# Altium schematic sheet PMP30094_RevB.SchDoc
size 431 x 279 mm; Date: Not shown in title block; ApprovedBy: Not shown in title block; CheckedBy: Not shown in title block; Author: Not shown in title block; CompanyName: Not shown in title block; Engineer: Not shown in title block; Organization: Not shown in title block; Address1: Not shown in title block; Address2: Not shown in title block; Address3: Not shown in title block; Address4: Not shown in title block; DocumentNumber: 1; Revision: Use project parameter SCH_Rev; SheetNumber: 2; SheetTotal: 3; PageSetup: Record=PageOptions¦CenterHorizontal=True¦CenterVertical=True¦PrintScale=0.64¦XCorrection=1.00¦YCorrection=1.00¦PrintKind=0¦BorderSize=5000000¦LeftOffset=0¦BottomOffset=0¦Orientation=2¦PaperLength=1000¦PaperWidth=1000¦Scale=100¦PaperSource=15¦PrintQuality=600¦MediaType=1¦DitherType=10¦PrintScaleMode=1¦PaperKind=Letter
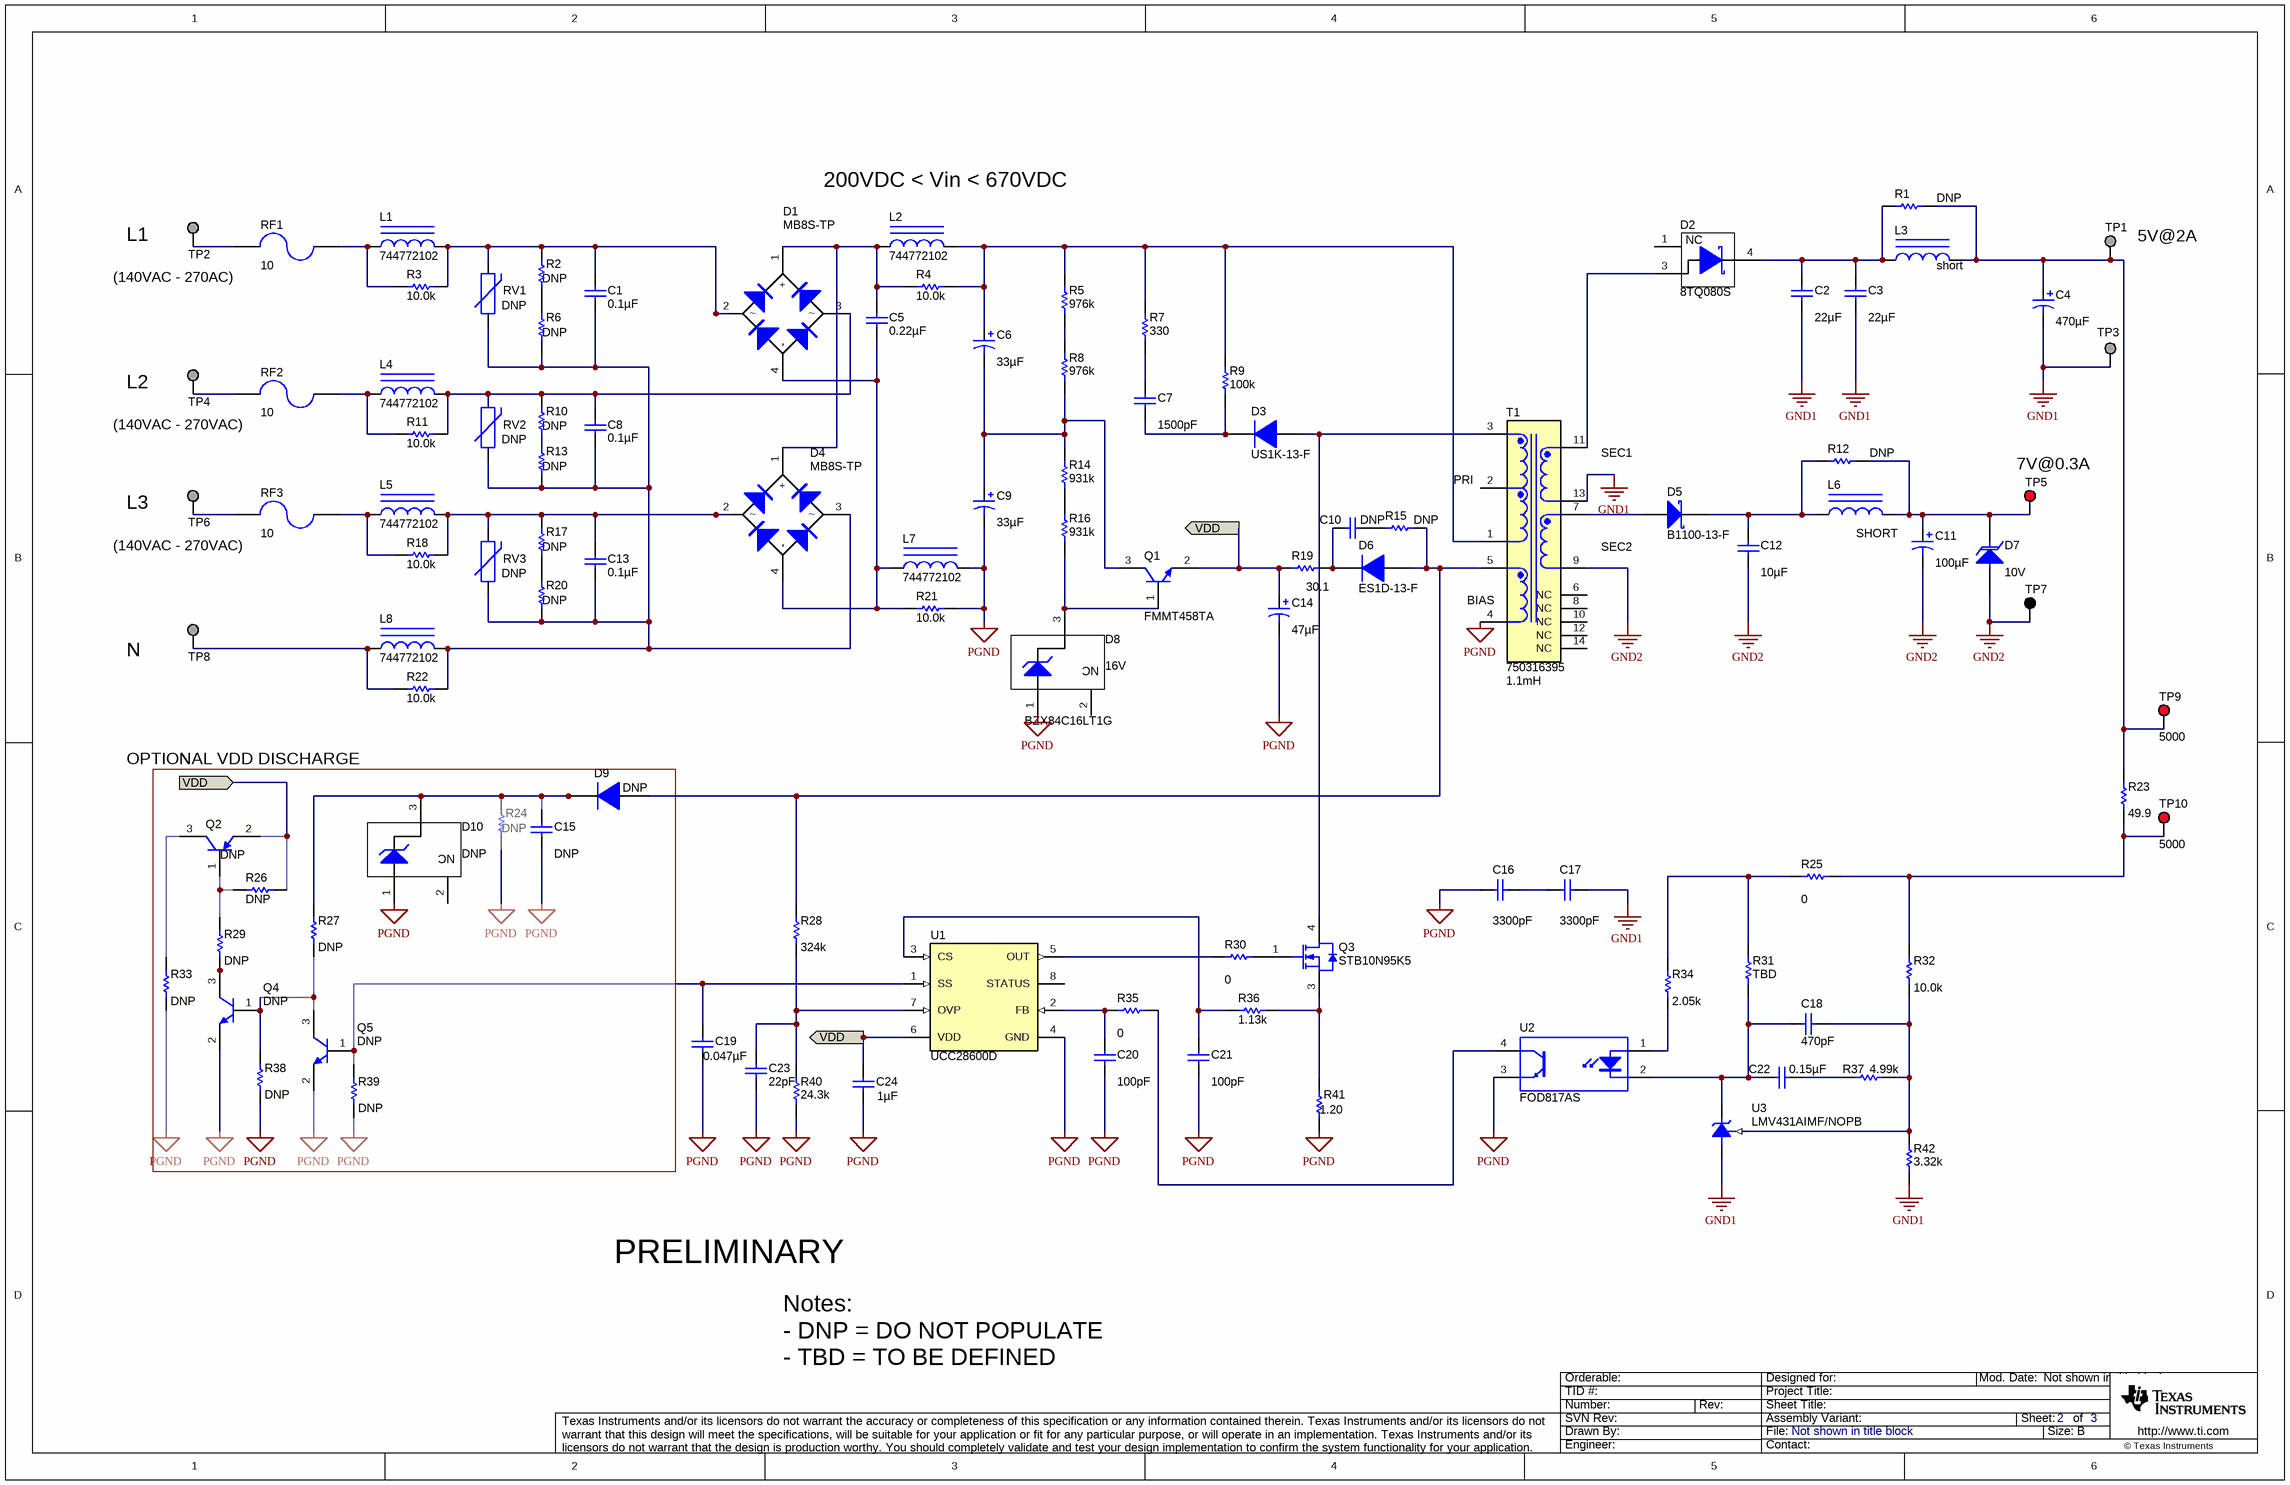
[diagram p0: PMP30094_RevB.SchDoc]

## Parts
C1  ValueDisplayed: 0.1µF  [B32921_1300x1200x600]  (hidden comment: B32921C3104M)
C2  ValueDisplayed: 22µF  [1206_180]  (hidden comment: GRM31CR71A226ME15L)
C3  ValueDisplayed: 22µF  [1206_180]  (hidden comment: GRM31CR71A226ME15L)
C4  ValueDisplayed: 470µF  [SM_RADIAL_F]  (hidden comment: EEE-FK1A471P)
C5  ValueDisplayed: 0.22µF  [B32653_2650x2050x1100]  (hidden comment: B32653A224J)
C6  ValueDisplayed: 33µF  [KMG_1600x2500]  (hidden comment: EKMG401ELL330ML25S)
C7  ValueDisplayed: 1500pF  [1206]  (hidden comment: GRM31BR73A152KW01L)
C8  ValueDisplayed: 0.1µF  [B32921_1300x1200x600]  (hidden comment: B32921C3104M)
C9  ValueDisplayed: 33µF  [KMG_1600x2500]  (hidden comment: EKMG401ELL330ML25S)
C10  value DNP  [0805]  (hidden comment: Used in BOM report)
C11  ValueDisplayed: 100µF  [SM_RADIAL_E]  (hidden comment: EEE-FC1A101P)
C12  ValueDisplayed: 10µF  [1206_190]  (hidden comment: C3216X7R1C106K160AC)
C13  ValueDisplayed: 0.1µF  [B32921_1300x1200x600]  (hidden comment: B32921C3104M)
C14  ValueDisplayed: 47µF  [SM_RADIAL_E]  (hidden comment: EEE-FC1V470P)
C15  ValueDisplayed: DNP  [0805_HV]  (hidden comment: GRM21BR71E225KA73L)
C16  ValueDisplayed: 3300pF  [KX_1000x700]  (hidden comment: DE1E3KX332MN4AP01F)
C17  ValueDisplayed: 3300pF  [KX_1000x700]  (hidden comment: DE1E3KX332MN4AP01F)
C18  ValueDisplayed: 470pF  [0402]  (hidden comment: GRM155R71H471KA01D)
C19  ValueDisplayed: 0.047µF  [0603]  (hidden comment: GRM188R71H473KA61D)
C20  ValueDisplayed: 100pF  [0603]  (hidden comment: GRM1885C1H101JA01D)
C21  ValueDisplayed: 100pF  [0603]  (hidden comment: GRM1885C1H101JA01D)
C22  ValueDisplayed: 0.15µF  [0603]  (hidden comment: C1608X7R1H154K080AB)
C23  ValueDisplayed: 22pF  [0603]  (hidden comment: 06035A220JAT2A)
C24  ValueDisplayed: 1µF  [0805_HV]  (hidden comment: 08055C105KAT2A)
D1  MB8S-TP  [MBS-1]
D2  8TQ080S  [DDPAK]
D3  US1K-13-F  [SMA]
D4  MB8S-TP  [MBS-1]
D5  B1100-13-F  [SMA]
D6  ES1D-13-F  [SMA]
D7  value 10V  [SMA]  (hidden comment: SMAJ10A)
D8  BZX84C16LT1G  value 16V  [SOT-23]
D9  value DNP  [SOD-123]  (hidden comment: BAV21W-7-F)
D10  value DNP  [SOT-23]  (hidden comment: BZX84C16LT1G)
L1  744772102  [WE_TI_8095_Unshielded]
L2  744772102  [WE_TI_8095_Unshielded]
L3  value short  [DO3308P]  (hidden comment: DO3308P-472MLB)
L4  744772102  [WE_TI_8095_Unshielded]
L5  744772102  [WE_TI_8095_Unshielded]
L6  value SHORT  [DO1608C]  (hidden comment: DO1608C-222MLB)
L7  744772102  [WE_TI_8095_Unshielded]
L8  744772102  [WE_TI_8095_Unshielded]
Q1  FMMT458TA  [SOT-23]
Q2  DNP  [SOT-23]
Q3  STB10N95K5  [DDPAK]
Q4  DNP  [SOT-23]
Q5  DNP  [SOT-23]
R1  value DNP  [0805]  (hidden comment: Used in BOM report)
R2  value DNP  [0805_HV]  (hidden comment: Used in BOM report)
R3  ValueDisplayed: 10.0k  [0805_HV]  (hidden comment: CRCW080510K0FKEA)
R4  ValueDisplayed: 10.0k  [0805_HV]  (hidden comment: CRCW080510K0FKEA)
R5  ValueDisplayed: 976k  [1206]  (hidden comment: CRCW1206976KFKEA)
R6  value DNP  [0805_HV]  (hidden comment: Used in BOM report)
R7  ValueDisplayed: 330  [2010]  (hidden comment: CRCW2010330RJNEF)
R8  ValueDisplayed: 976k  [1206]  (hidden comment: CRCW1206976KFKEA)
R9  ValueDisplayed: 100k  [2010]  (hidden comment: CRCW2010100KFKEF)
R10  value DNP  [0805]  (hidden comment: Used in BOM report)
R11  ValueDisplayed: 10.0k  [0805_HV]  (hidden comment: CRCW080510K0FKEA)
R12  value DNP  [0805]  (hidden comment: Used in BOM report)
R13  value DNP  [0805_HV]  (hidden comment: Used in BOM report)
R14  ValueDisplayed: 931k  [1206]  (hidden comment: CRCW1206931KFKEA)
R15  value DNP  [1206]  (hidden comment: Used in BOM report)
R16  ValueDisplayed: 931k  [1206]  (hidden comment: CRCW1206931KFKEA)
R17  value DNP  [0805_HV]  (hidden comment: Used in BOM report)
R18  ValueDisplayed: 10.0k  [0805_HV]  (hidden comment: CRCW080510K0FKEA)
R19  ValueDisplayed: 30.1  [0805_HV]  (hidden comment: CRCW080530R1FKEA)
R20  value DNP  [0805_HV]  (hidden comment: Used in BOM report)
R21  ValueDisplayed: 10.0k  [0805_HV]  (hidden comment: CRCW080510K0FKEA)
R22  ValueDisplayed: 10.0k  [0805_HV]  (hidden comment: CRCW080510K0FKEA)
R23  ValueDisplayed: 49.9  [0603]  (hidden comment: CRCW060349R9FKEA)
R24  value DNP  [1206]  (hidden comment: Used in BOM report)
R25  ValueDisplayed: 0  [0603]  (hidden comment: CRCW06030000Z0EA)
R26  ValueDisplayed: DNP  [0603]  (hidden comment: CRCW0603100KFKEA)
R27  ValueDisplayed: DNP  [0603]  (hidden comment: CRCW0603100KFKEA)
R28  ValueDisplayed: 324k  [0603]  (hidden comment: CRCW0603324KFKEA)
R29  ValueDisplayed: DNP  [0603]  (hidden comment: CRCW0603100KFKEA)
R30  ValueDisplayed: 0  [0805_HV]  (hidden comment: CRCW08050000Z0EA)
R31  value TBD  [0603]  (hidden comment: Used in BOM report)
R32  ValueDisplayed: 10.0k  [0603]  (hidden comment: RCG060310K0FKEA)
R33  ValueDisplayed: DNP  [1206]  (hidden comment: CRCW12061K00FKEA)
R34  ValueDisplayed: 2.05k  [0603]  (hidden comment: CRCW06032K05FKEA)
R35  ValueDisplayed: 0  [0603]  (hidden comment: CRCW06030000Z0EA)
R36  ValueDisplayed: 1.13k  [0603]  (hidden comment: CRCW06031K13FKEA)
R37  ValueDisplayed: 4.99k  [0603]  (hidden comment: CRCW06034K99FKEA)
R38  ValueDisplayed: DNP  [0603]  (hidden comment: CRCW0603100KFKEA)
R39  ValueDisplayed: DNP  [0603]  (hidden comment: CRCW0603100KFKEA)
R40  ValueDisplayed: 24.3k  [0603]  (hidden comment: RC0603FR-0724K3L)
R41  ValueDisplayed: 1.20  [0805_HV]  (hidden comment: ERJ-6RQF1R2V)
R42  ValueDisplayed: 3.32k  [0603]  (hidden comment: CRCW06033K32FKEA)
RF1  ValueDisplayed: 10  [RES_PWR4522]  (hidden comment: FW20A10R0JACT-ND)
RF2  ValueDisplayed: 10  [RES_PWR4522]  (hidden comment: FW20A10R0JACT-ND)
RF3  ValueDisplayed: 10  [RES_PWR4522]  (hidden comment: FW20A10R0JACT-ND)
RV1  value DNP  [VAR_S10K275E2]  (hidden comment: S10K275E2)
RV2  value DNP  [VAR_S10K275E2]  (hidden comment: S10K275E2)
RV3  value DNP  [VAR_S10K275E2]  (hidden comment: S10K275E2)
T1  750316395  ValueDisplayed: 1.1mH  [Wurth_750316395]
TP1  Suggest using a net name here  [Keystone1503-2]  (value not drawn)
TP2  Suggest using a net name here  [Keystone1503-2]  (value not drawn)
TP3  Suggest using a net name here  [Keystone1503-2]  (value not drawn)
TP4  Suggest using a net name here  [Keystone1503-2]  (value not drawn)
TP5  5000  [Keystone5000]  (value not drawn)
TP6  Suggest using a net name here  [Keystone1503-2]  (value not drawn)
TP7  5001  [Keystone5001]  (value not drawn)
TP8  Suggest using a net name here  [Keystone1503-2]  (value not drawn)
TP9  5000  [Keystone5000]
TP10  5000  [Keystone5000]
U1  UCC28600D  [D0008A_N]
U2  FOD817AS  [N04C]
U3  LMV431AIMF/NOPB  [MF03A_N]

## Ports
VDD (in), VDD (out)

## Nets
GND1: C2.1 C3.1 C4.2(-) C17.1 R42.1 T1.13 TP3.1 U3.3(A)
GND2: C11.2(-) C12.2 D7.2(A) T1.9 TP7.1
PGND: C9.2(-) C14.2(-) C15.2 C16.2 C19.2 C20.2 C21.2 C23.2 C24.2 D8.1(A) D10.1(A) L7.2 Q4.2(E) Q5.2(E) R21.2 R24.1 R33.1 R38.1 R39.1 R40.1 R41.1 T1.4 U1.4(GND) U2.3(E)
VDD: C14.1(+) C24.1 Q1.2(E) Q2.2(E) R19.1 R26.1 U1.6(VDD) ; port VDD
NetC1_1: C1.1 D1.2 L1.2 R2.2 R3.2 RV1.2
NetC1_2: C1.2 C8.2 C13.2 D4.3 L8.2 R6.1 R13.1 R20.1 R22.2 RV1.1 RV2.1 RV3.1
NetC2_2: C2.2 C3.2 D2.4(K) L3.1 R1.1
NetC4_1: C4.1(+) L3.2 R1.2 R23.2 TP1.1 TP9.1
NetC5_1: C5.1 D1.1(+) D4.1(+) L2.1 R4.1
NetC5_2: C5.2 D1.4(-) D4.4(-) L7.1 R21.1
NetC6_1: C6.1(+) L2.2 R4.2 R5.2 R7.2 R9.2 T1.1
NetC6_2: C6.2(-) C9.1(+) Q1.3(C) R8.1 R14.2
NetC7_1: C7.1 R7.1
NetC7_2: C7.2 D3.1(K) R9.1
NetC8_1: C8.1 D1.3 L4.2 R10.2 R11.2 RV2.2
NetC10_1: C10.1 R15.1
NetC10_2: C10.2 D6.1(K) R19.2
NetC11_1: C11.1(+) D7.1(K) L6.2 R12.2 TP5.1
NetC12_1: C12.1 D5.1(K) L6.1 R12.1
NetC13_1: C13.1 D4.2 L5.2 R17.2 R18.2 RV3.2
NetC15_1: C15.1 D9.1(K) D10.3(K) R24.2 R27.2
NetC16_1: C16.1 C17.2
NetC18_1: C18.1 R32.1 R37.2 R42.2 U3.1(REF)
NetC18_2: C18.2 C22.2 R31.1 U2.2(K) U3.2(K)
NetC19_1: C19.1 Q5.1(B) R39.2 U1.1(SS)
NetC20_1: C20.1 R35.1 U1.2(FB)
NetC21_1: C21.1 R36.1 U1.3(CS)
NetC22_1: C22.1 R37.1
NetC23_1: C23.1 R28.1 R40.2 U1.7(OVP)
NetD2_3: D2.3(A) T1.11
NetD3_2: D3.2(A) Q3.4(D) T1.3
NetD5_2: D5.2(A) T1.7
NetD6_2: D6.2(A) D9.2(A) R15.2 R28.2 T1.5
NetD8_3: D8.3(K) Q1.1(B) R16.1
NetL1_1: L1.1 R3.1 RF1.1
NetL4_1: L4.1 R11.1 RF2.1
NetL5_1: L5.1 R18.1 RF3.1
NetL8_1: L8.1 R22.1 TP8.1
NetQ2_1: Q2.1(B) R26.2 R29.2
NetQ2_3: Q2.3(C) R33.2
NetQ3_1: Q3.1(G) R30.2
NetQ3_3: Q3.3(S) R36.2 R41.2
NetQ4_1: Q4.1(B) Q5.3(C) R27.1 R38.2
NetQ4_3: Q4.3(C) R29.1
NetR2_1: R2.1 R6.2
NetR5_1: R5.1 R8.2
NetR10_1: R10.1 R13.2
NetR14_1: R14.1 R16.2
NetR17_1: R17.1 R20.2
NetR23_1: R23.1 R25.2 R32.2 TP10.1
NetR25_1: R25.1 R31.2 R34.2
NetR30_1: R30.1 U1.5(OUT)
NetR34_1: R34.1 U2.1(A)
NetR35_2: R35.2 U2.4(C)
NetRF1_2: RF1.2 TP2.1
NetRF2_2: RF2.2 TP4.1
NetRF3_2: RF3.2 TP6.1

Not connected (* = marked no-connect by the designer): D2 1(NC); D8 2(NC); D10 2(NC); T1 2 6(NC) 8(NC) 10(NC) 12(NC) 14(NC); U1 8(STATUS)

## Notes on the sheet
- 200VDC < Vin < 670VDC
- (140VAC - 270AC)
- (near TP2) L1
- (near TP1) 5V@2A
- (140VAC - 270VAC)
- (near TP4) L2
- PRI
- (near T1) SEC1
- (near TP5) 7V@0.3A
- (near TP6) L3
- SEC2
- (near T1) BIAS
- N
- OPTIONAL VDD DISCHARGE
- PRELIMINARY
- Notes:
- - DNP = DO NOT POPULATE
- - TBD = TO BE DEFINED

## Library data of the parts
C1 C8 C13 = B32921C3104M: CAP, Film, 0.1 µF, 305 V, +/- 20%, TH; Manufacturer: EPCOS Inc; Polarized: N; CompType: Capacitor; Value: 0.1uF; U/M: EA; Cap_F: 0.0000001; Tolerance_%: 20; Value1: Unknown; VDC_V: 305; Value2: 305V; TaMin_C: -40; TaMax_C: 110; Cap_Case: 13x12x6mm
C2 C3 = GRM31CR71A226ME15L: CAP, CERM, 22 µF, 10 V, +/- 20%, X7R, 1206; Manufacturer: MuRata; Polarized: N; CompType: Capacitor; Value: 22uF; U/M: EA; Cap_F: 0.000022; Tolerance_%: 20; Value1: Unknown; VDC_V: 10; Value2: 10V; TaMin_C: -55; TaMax_C: 125; Cap_Case: 1206; SizeArea_mm2: 5.12; SizeAreaWB_mm2: 10.92; SizeX_mm: 3.2; SizeY_mm: 1.6; SizeZ_mm: 1.8; AEC Category: Q200
C4 = EEE-FK1A471P: CAP, AL, 470 µF, 10 V, +/- 20%, 0.16 ohm, SMD; Manufacturer: Panasonic; Polarized: Y; CompType: Capacitor; Value: 470uF; U/M: EA; Cap_F: 0.00047; Tolerance_%: 20; VDC_V: 10; Value2: 10V; ESR_ohm: 0.16; IRMS_A: 0.6; TaMin_C: -55; TaMax_C: 105; Cap_Case: F; AEC Category: Q200
C5 = B32653A224J: CAP, Film, 0.22 µF, 1000 V, +/- 5%, TH; Manufacturer: EPCOS Inc; Polarized: N; CompType: Capacitor; Value: 0.22uF; U/M: EA; Cap_F: 0.00000022; Tolerance_%: 5; Value1: Unknown; VDC_V: 1000; Value2: 1000V; TaMin_C: -55; TaMax_C: 110; Cap_Case: 26.5x20.5x11mm
C6 C9 = EKMG401ELL330ML25S: CAP, AL, 33 µF, 400 V, +/- 20%, TH; Manufacturer: Chemi-Con; Polarized: Y; CompType: Capacitor; Value: 33uF; U/M: EA; Cap_F: 0.000033; Tolerance_%: 20; Value1: Unknown; VDC_V: 400; Value2: 400V; IRMS_A: 0.195; TaMin_C: -40; TaMax_C: 105; Cap_Case: 16x25mm; AEC Category: Q200; AEC Qualified: N
C7 = GRM31BR73A152KW01L: CAP, CERM, 1500 pF, 1000 V, +/- 10%, X7R, 1206; Manufacturer: MuRata; Polarized: N; CompType: Capacitor; Value: 1500pF; U/M: EA; Cap_F: 0.0000000015; Tolerance_%: 10; Value1: Unknown; VDC_V: 1000; Value2: 1000V; TaMin_C: -55; TaMax_C: 125; SizeArea_mm2: 5.12; SizeAreaWB_mm2: 10.92; SizeX_mm: 3.2; SizeY_mm: 1.6; SizeZ_mm: 1.35; AEC Category: Q200
C10 = Capacitor: CAP, CERM, xxxF, xxV, [TempCo], xx%, [PackageReference]; Polarized: N; U/M: EA
C11 = EEE-FC1A101P: CAP, AL, 100 µF, 10 V, +/- 20%, 0.4 ohm, SMD; Manufacturer: Panasonic; Polarized: Y; CompType: Capacitor; Value: 100uF; U/M: EA; Cap_F: 0.0001; Tolerance_%: 20; Value1: 0.4 ohm; VDC_V: 10; Value2: 10V; ESR_ohm: 0.4; IRMS_A: 0.15; TaMin_C: -40; TaMax_C: 105; Cap_Case: E; AEC Category: Q200
C12 = C3216X7R1C106K160AC: CAP, CERM, 10 µF, 16 V, +/- 10%, X7R, 1206_190; Manufacturer: TDK; Polarized: N; CompType: Capacitor; Value: 10uF; U/M: EA; Cap_F: 0.00001; Tolerance_%: 10; Value1: Unknown; VDC_V: 16; Value2: 16V; TaMin_C: -55; TaMax_C: 125; Cap_Case: 1206; SizeArea_mm2: 5.12; SizeAreaWB_mm2: 10.92; SizeX_mm: 3.2; SizeY_mm: 1.6; SizeZ_mm: 1.9; AEC Category: Q200
C14 = EEE-FC1V470P: CAP, AL, 47 µF, 35 V, +/- 20%, 0.4 ohm, SMD; Manufacturer: Panasonic; Polarized: Y; CompType: Capacitor; Value: 47uF; U/M: EA; Cap_F: 0.000047; Tolerance_%: 20; Value1: 0.4 ohm; VDC_V: 35; Value2: 35V; ESR_ohm: 0.4; IRMS_A: 0.15; TaMin_C: -40; TaMax_C: 105; Cap_Case: E; AEC Category: Q200
C15 = GRM21BR71E225KA73L: CAP, CERM, 2.2 µF, 25 V, +/- 10%, X7R, 0805; Manufacturer: MuRata; Polarized: N; CompType: Capacitor; Value: 2.2uF; U/M: EA; Cap_F: 0.0000022; Tolerance_%: 10; ESR_ohm: 0.005; Value1: 0.005 ohm; VDC_V: 25; Value2: 25V; TaMin_C: -55; TaMax_C: 125; Cap_Case: 0805; SizeArea_mm2: 2.5; SizeAreaWB_mm2: 6.75; SizeX_mm: 2; SizeY_mm: 1.25; SizeZ_mm: 1.45; AEC Category: Q200
C16 C17 = DE1E3KX332MN4AP01F: CAP, CERM, 3300 pF, 300 V, +/- 20%, E, D10xT7mm; Manufacturer: MuRata; Polarized: N; CompType: Capacitor; Value: 3300pF; U/M: EA; Cap_F: 0.0000000033; Tolerance_%: 20; Value1: Unknown; VDC_V: 300; Value2: 300V; TaMin_C: -40; TaMax_C: 125; Cap_Case: 10x7mm; SizeArea_mm2: 70; SizeAreaWB_mm2: 108; SizeX_mm: 10; SizeY_mm: 7; SizeZ_mm: 13; AEC Category: Q200
C18 = GRM155R71H471KA01D: CAP, CERM, 470 pF, 50 V, +/- 10%, X7R, 0402; Manufacturer: MuRata; Polarized: N; CompType: Capacitor; Value: 470pF; U/M: EA; Cap_F: 0.00000000047; Tolerance_%: 10; Value1: Unknown; VDC_V: 50; Value2: 50V; TaMin_C: -55; TaMax_C: 125; SizeArea_mm2: 0.5; SizeAreaWB_mm2: 3; SizeX_mm: 1; SizeZ_mm: 0.6; AEC Category: Q200
C19 = GRM188R71H473KA61D: CAP, CERM, 0.047 µF, 50 V, +/- 10%, X7R, 0603; Manufacturer: MuRata; Polarized: N; CompType: Capacitor; Value: 0.047uF; U/M: EA; Cap_F: 0.000000047; Tolerance_%: 10; Value1: Unknown; VDC_V: 50; Value2: 50V; TaMin_C: -55; TaMax_C: 125; SizeArea_mm2: 1.28; SizeAreaWB_mm2: 4.68; SizeX_mm: 1.6; SizeY_mm: 0.8; SizeZ_mm: 1; AEC Category: Q200
C20 C21 = GRM1885C1H101JA01D: CAP, CERM, 100 pF, 50 V, +/- 5%, C0G/NP0, 0603; Manufacturer: MuRata; Polarized: N; CompType: Capacitor; Value: 100pF; U/M: EA; Cap_F: 0.0000000001; Tolerance_%: 5; Value1: Unknown; VDC_V: 50; Value2: 50V; TaMin_C: -55; TaMax_C: 125; SizeArea_mm2: 1.28; SizeAreaWB_mm2: 4.68; SizeX_mm: 1.6; SizeY_mm: 0.8; SizeZ_mm: 1; AEC Category: Q200
C22 = C1608X7R1H154K080AB: CAP, CERM, 0.15 µF, 50 V, +/- 10%, X7R, 0603; Manufacturer: TDK; Polarized: N; CompType: Capacitor; Value: 0.15uF; U/M: EA; Cap_F: 0.00000015; Tolerance_%: 10; ESR_ohm: 0.028863; Value1: 0.028863 ohm; VDC_V: 50; Value2: 50V; IRMS_A: 0.978809; TaMin_C: -55; TaMax_C: 125; SizeArea_mm2: 1.28; SizeAreaWB_mm2: 4.68; SizeX_mm: 1.6; SizeY_mm: 0.8; SizeZ_mm: 1; AEC Category: Q200
C23 = 06035A220JAT2A: CAP, CERM, 22 pF, 50 V, +/- 5%, C0G/NP0, 0603; Manufacturer: AVX; Polarized: N; CompType: Capacitor; Value: 22pF; U/M: EA; Cap_F: 0.000000000022; Tolerance_%: 5; ESR_ohm: 0.259; Value1: 0.259 ohm; VDC_V: 50; Value2: 50V; TaMin_C: -55; TaMax_C: 125; SizeArea_mm2: 1.28; SizeAreaWB_mm2: 4.68; SizeX_mm: 1.6; SizeY_mm: 0.8; SizeZ_mm: 1; AEC Category: Q200
C24 = 08055C105KAT2A: CAP, CERM, 1 µF, 50 V, +/- 10%, X7R, 0805; Manufacturer: AVX; Polarized: N; CompType: Capacitor; Value: 1uF; U/M: EA; Cap_F: 0.000001; Tolerance_%: 10; Value1: Unknown; VDC_V: 50; Value2: 50V; TaMin_C: -55; TaMax_C: 125; Cap_Case: 0805; SizeArea_mm2: 2.5; SizeAreaWB_mm2: 6.75; SizeX_mm: 2; SizeY_mm: 1.25; SizeZ_mm: 1.45; AEC Category: Q200
D1 D4 = MB8S-TP: Diode, Switching-Bridge, 800 V, 0.5 A, 4-Pin TO269AA, Body 4.95 x 4.2 mm, Pitch 2.555 mm; Manufacturer: Micro Commercial Components; U/M: EA; Vf_V: 1; Value: 800V; Value1: 0.5A; Value2: 1V; Io_A: 0.5; Vr_V: 800; TJmax_C: 150
D2 = MBRB745PBF: Diode, Schottky, 80V, 8A, DDPAK; Manufacturer: Vishay-Semiconductor; U/M: EA; Vf_V: 0.7; Value2: 0.7V; Io_A: 7.5; Vr_V: 45; TJmax_C: 150; RJC_CperW: 3; SizeAreaWB_mm2: 209.6992; SizeArea_mm2: 154.8892; SizeX_mm: 15.245; SizeY_mm: 10.16; SizeZ_mm: 4.445; AEC Category: Q101; Speed: Fast Recovery =< 500ns, > 200mA (Io); Current - Reverse Leakage @ Vr: 4.5µA @ 100V; Capacitance @ Vr, F: 600pF @ 4V, 1MHz
D3 = US1K-13-F: Diode, Fast Rectifier, 800 V, 1 A, SMA; Manufacturer: Diodes Inc.; U/M: EA; Vf_V: 1.7; Value: 800V; Value1: 1A; Value2: 1.7V; Io_A: 1; Vr_V: 800; TJmax_C: 150; SizeAreaWB_mm2: 37.3428; SizeArea_mm2: 16.3228; SizeX_mm: 5.59; SizeY_mm: 2.92; SizeZ_mm: 2.87; AEC Category: Q101
D5 = B1100-13-F: Diode, Schottky, 100 V, 1 A, SMA; Manufacturer: Diodes Inc.; U/M: EA; Vf_V: 0.79; Value: 100V; Value1: 1A; Value2: 0.79V; Io_A: 1; Vr_V: 100; TJmax_C: 150; RJC_CperW: 25; SizeAreaWB_mm2: 37.3428; SizeArea_mm2: 16.3228; SizeX_mm: 5.59; SizeY_mm: 2.92; SizeZ_mm: 2.87; AEC Category: Q101
D6 = ES1D-13-F: Diode, Ultrafast, 200 V, 1 A, SMA; Manufacturer: Diodes Inc.; U/M: EA; Vf_V: 0.92; Value: 200V; Value1: 1A; Value2: 0.92V; Io_A: 1; Vr_V: 200; TJmax_C: 150; RJC_CperW: 25; SizeAreaWB_mm2: 37.3428; SizeArea_mm2: 16.3228; SizeX_mm: 5.59; SizeY_mm: 2.92; SizeZ_mm: 2.87; AEC Category: Q101
D7 = SMAJ10A: Diode, TVS, Uni, 10 V, 400 W, SMA; Manufacturer: Littelfuse; U/M: EA; Power_W: 400; Vr_V: 10; Value1: 400W; RJA_CperW: 120; SizeAreaWB_mm2: 37.3428; SizeArea_mm2: 16.3228; SizeX_mm: 5.59; SizeY_mm: 2.92; SizeZ_mm: 2.87; AEC Category: Q101
D8 D10 = BZX84C16LT1G: Diode, Zener, 16 V, 225 mW, SOT-23; Manufacturer: ON Semiconductor; U/M: EA; Power_W: 0.225; Vz_V: 16; Value1: 0.225W; RJA_CperW: 556; SizeAreaWB_mm2: 14; SizeArea_mm2: 7.5; SizeX_mm: 2.5; SizeY_mm: 3; SizeZ_mm: 1.1; AEC Category: Q101
D9 = BAV21W-7-F: Diode, Switching, 200 V, 0.2 A, SOD-123; Manufacturer: Diodes Inc.; U/M: EA; Vf_V: 1.25; Value1: 0.2A; Value2: 1.25V; Io_A: 0.2; Vr_V: 200; TJmax_C: 150; SizeAreaWB_mm2: 13.095; SizeArea_mm2: 6.545; SizeX_mm: 3.85; SizeY_mm: 1.7; SizeZ_mm: 1.35; AEC Category: Q101
L1 L2 L4 L5 L7 L8 = 744772221: Inductor, Wirewound, Ferrite, 1000µH, TH; Manufacturer: Wurth Elektronik; Value: 1000uH; Ind_H: 220.0E-6; AEC Category: Q200
L3 = DO3308P-472MLB: Inductor, Drum Core, Ferrite, 4.7 µH, 3.2 A, 0.04 ohm, SMD; Manufacturer: Coilcraft; ValueDisplayed: 4.7µH; Ind_H: 4.7E-6; Imax_A: 3.2; Irms: 3.2A @ 40C rise; Isat: 4.2A @ 10% inductance drop; DCR_ohm: 0.04; Value2: 3.2A; AEC Category: Q200
L6 = DO1608C-222MLB: Inductor, Drum Core, Ferrite, 2.2 µH, 2.3 A, 0.07 ohm, SMD; Manufacturer: Coilcraft; ValueDisplayed: 2.2µH; Ind_H: 2.2E-6; Imax_A: 2.3; Irms: 2.55A @ 15C rise; Isat: 2.3A @ 10% inductance drop; DCR_ohm: 0.07; Value2: 2.3A; AEC Category: Q200
Q1 = FMMT458TA, Diodes Inc.: Transistor, NPN, 400 V, 0.225 A, SOT-23; CompType: BJT; PNP: 0; NPN: 1; Vceo_V: 400; Vcesat1_V: 0.2; Value: 400 V; IcRated_A: 0.225; Value1: 0.225 A; HfeMax: 300; TaMin_C: -55; TaMax_C: 150; U/M: EA; AEC Category: Q101; AEC Qualified: N
Q2 = MMBT3906, Fairchild Semiconductor: Transistor, PNP, 40 V, 0.2 A, SOT-23; CompType: BJT; PNP: 1; NPN: 0; Vceo_V: 40; Vcesat1_V: 0.25; Value: 40 V; IcRated_A: 0.2; Value1: 0.2 A; HfeMax: 300; TaMin_C: -55; TaMax_C: 150; U/M: EA; AEC Category: Q101
Q3 = STB8N65M5: MOSFET, N-CH, 950 V, DDPAK; Manufacturer: STMicroelectronics; Alternate Manufacturer: None; U/M: EA; ChType: N; Value: 950V; VdsMax_V: 710; Value1: ? ohm; Value2: 15 nC; QgTyp_nC: 15; Vgs_V: 25; IdsMax_A: 7; SizeAreaWB_mm2: 209.6992; SizeArea_mm2: 154.8892; SizeX_mm: 15.245; SizeY_mm: 10.16; SizeZ_mm: 4.445; AEC Category: Q101; FET Type: MOSFET N-Channel, Metal Oxide; FET Feature: Standard; Current - Continuous Drain (Id) @ 25°C: 8A (Tc); Rds On (Max) @ Id, Vgs: 800 mOhm @ 4A, 10V; Vgs(th) (Max) @ Id: 5V @ 100µA; Gate Charge (Qg) @ Vgs: 22nC @ 10V; Input Capacitance (Ciss) @ Vds: 630pF @ 100V; Power - Max: 130W
Q4 Q5 = MMBT3904, Fairchild Semiconductor: Transistor, NPN, 40 V, 0.2 A, SOT-23; CompType: BJT; PNP: 0; NPN: 1; Vceo_V: 40; Vcesat1_V: 0.2; Value: 40 V; Value1: 0.2 A; HfeMax: 300; TaMin_C: -55; TaMax_C: 150; U/M: EA; AEC Category: Q101
R1 R2 R6 R10 R12 R13 R15 R17 R20 R24 R31 = Resistor: RES, xxx ohm, x%, xW, [PackageReference]; U/M: EA
R3 R4 R11 R18 R21 R22 = CRCW080510K0FKEA: RES, 10.0 k, 1%, 0.125 W, 0805; Manufacturer: Vishay-Dale; CompType: Resistor; Value: 10.0k; Res_ohm: 10000; Value_Code: 10k0; Tolerance_%: 1; Power_W: 0.125; Value2: 0.125W; VDC_V: 150; TempCo: 100 ppm/C; EIA_Code: E96; U/M: EA
R5 R8 = CRCW1206976KFKEA: RES, 976 k, 1%, 0.25 W, 1206; Manufacturer: Vishay-Dale; CompType: Resistor; Value: 976k; Res_ohm: 976000; Tolerance_%: 1; Power_W: 0.25; Value2: 0.25W; VDC_V: 200; TempCo: 100 ppm/C; EIA_Code: E96; U/M: EA; SizeArea_mm2: 5.12; SizeX_mm: 3.2; SizeY_mm: 1.6; SizeZ_mm: 1.35; AEC Category: Q200
R7 = CRCW2010330RJNEF: RES, 330, 5%, 0.75 W, AEC-Q200 Grade 0, 2010; Manufacturer: Vishay-Dale; CompType: Resistor; Value: 330; Value_Code: 330R; Tolerance_%: 5; Power_W: 0.75; Value2: 0.75W; VDC_V: 400; TempCo: 200 ppm/C; EIA_Code: E24; U/M: EA; AEC Category: Q200; AEC Qualified: Y; AEC Grade: 0; SizeArea_mm2: 12.5; SizeY_mm: 2.5; SizeZ_mm: 1.66
R9 = CRCW2010100KFKEF: RES, 100 k, 1%, 0.75 W, 2010; Manufacturer: Vishay-Dale; CompType: Resistor; Value: 100k; Res_ohm: 100000; Tolerance_%: 1; Power_W: 0.75; Value2: 0.75W; VDC_V: 400; TempCo: 100 ppm/C; EIA_Code: E96; U/M: EA; AEC Category: Q200
R14 R16 = CRCW1206931KFKEA: RES, 931 k, 1%, 0.25 W, 1206; Manufacturer: Vishay-Dale; CompType: Resistor; Value: 931k; Res_ohm: 931000; Tolerance_%: 1; Power_W: 0.25; Value2: 0.25W; VDC_V: 200; TempCo: 100 ppm/C; EIA_Code: E96; U/M: EA; SizeArea_mm2: 5.12; SizeX_mm: 3.2; SizeY_mm: 1.6; SizeZ_mm: 1.35; AEC Category: Q200
R19 = CRCW080530R1FKEA: RES, 30.1, 1%, 0.125 W, 0805; Manufacturer: Vishay-Dale; CompType: Resistor; Value: 30.1; Value_Code: 30R1; Tolerance_%: 1; Power_W: 0.125; Value2: 0.125W; VDC_V: 150; TempCo: 100 ppm/C; SizeArea_mm2: 2.5; SizeX_mm: 2; SizeY_mm: 1.25; SizeZ_mm: 1.45; EIA_Code: E96; U/M: EA; AEC Category: Q200
R23 = CRCW060349R9FKEA: RES, 49.9, 1%, 0.1 W, 0603; Manufacturer: Vishay-Dale; CompType: Resistor; Value: 49.9; Value_Code: 49R9; Tolerance_%: 1; Power_W: 0.1; Value2: 0.1W; VDC_V: 75; TempCo: 100 ppm/C; SizeArea_mm2: 1.28; SizeX_mm: 1.6; SizeY_mm: 0.8; EIA_Code: E96; U/M: EA; AEC Category: Q200
R25 R35 = CRCW06030000Z0EA: RES, 0, 5%, 0.1 W, 0603; Manufacturer: Vishay-Dale; CompType: Resistor; Value: 0; Value_Code: 0000; Tolerance_%: 5; Power_W: 0.1; Value2: 0.1W; VDC_V: 75; TempCo: 200 ppm/C; SizeArea_mm2: 1.28; SizeX_mm: 1.6; SizeY_mm: 0.8; SizeZ_mm: 1; EIA_Code: E24; U/M: EA; AEC Category: Q200
R26 R27 R29 R38 R39 = CRCW0603100KFKEA: RES, 100 k, 1%, 0.1 W, 0603; Manufacturer: Vishay-Dale; CompType: Resistor; Value: 100k; Res_ohm: 100000; Tolerance_%: 1; Power_W: 0.1; Value2: 0.1W; VDC_V: 75; TempCo: 100 ppm/C; SizeArea_mm2: 1.28; SizeX_mm: 1.6; SizeY_mm: 0.8; EIA_Code: E96; U/M: EA; AEC Category: Q200
R28 = CRCW0603324KFKEA: RES, 324 k, 1%, 0.1 W, 0603; Manufacturer: Vishay-Dale; CompType: Resistor; Value: 324k; Res_ohm: 324000; Tolerance_%: 1; Power_W: 0.1; Value2: 0.1W; VDC_V: 75; TempCo: 100 ppm/C; SizeArea_mm2: 1.28; SizeX_mm: 1.6; SizeY_mm: 0.8; EIA_Code: E96; U/M: EA; AEC Category: Q200
R30 = CRCW08050000Z0EA: RES, 0, 5%, 0.125 W, 0805; Manufacturer: Vishay-Dale; CompType: Resistor; Value: 0; Value_Code: 0000; Tolerance_%: 5; Power_W: 0.125; Value2: 0.125W; VDC_V: 150; TempCo: 200 ppm/C; SizeArea_mm2: 2.5; SizeX_mm: 2; SizeY_mm: 1.25; SizeZ_mm: 1.45; EIA_Code: E24; U/M: EA; AEC Category: Q200
R32 = RCG060310K0FKEA: RES, 10.0 k, 1%, 0.1 W, 0603; Manufacturer: Vishay Draloric; CompType: Resistor; Value: 10.0k; Res_ohm: 10000; Value_Code: 10k0; Tolerance_%: 1; Power_W: 0.1; Value2: 0.1W; VDC_V: 75; TempCo: 100 ppm/C; SizeArea_mm2: 1.28; SizeX_mm: 1.6; SizeY_mm: 0.8; EIA_Code: E96; U/M: EA; AEC Category: Q200; AEC Qualified: N
R33 = CRCW12061K00FKEA: RES, 1.00 k, 1%, 0.25 W, 1206; Manufacturer: Vishay-Dale; CompType: Resistor; Value: 1.00k; Res_ohm: 1000; Value_Code: 1k00; Tolerance_%: 1; Power_W: 0.25; Value2: 0.25W; VDC_V: 200; TempCo: 100 ppm/C; SizeArea_mm2: 5.12; SizeX_mm: 3.2; SizeY_mm: 1.6; SizeZ_mm: 1.35; EIA_Code: E96; U/M: EA; AEC Category: Q200
R34 = CRCW06032K05FKEA: RES, 2.05 k, 1%, 0.1 W, 0603; Manufacturer: Vishay-Dale; CompType: Resistor; Value: 2.05k; Res_ohm: 2050; Value_Code: 2k05; Tolerance_%: 1; Power_W: 0.1; Value2: 0.1W; VDC_V: 75; TempCo: 100 ppm/C; SizeArea_mm2: 1.28; SizeX_mm: 1.6; SizeY_mm: 0.8; EIA_Code: E96; U/M: EA; AEC Category: Q200
R36 = CRCW06031K13FKEA: RES, 1.13 k, 1%, 0.1 W, 0603; Manufacturer: Vishay-Dale; CompType: Resistor; Value: 1.13k; Res_ohm: 1130; Value_Code: 1k13; Tolerance_%: 1; Power_W: 0.1; Value2: 0.1W; VDC_V: 75; TempCo: 100 ppm/C; SizeArea_mm2: 1.28; SizeX_mm: 1.6; SizeY_mm: 0.8; EIA_Code: E96; U/M: EA; AEC Category: Q200
R37 = CRCW06034K99FKEA: RES, 4.99 k, 1%, 0.1 W, 0603; Manufacturer: Vishay-Dale; CompType: Resistor; Value: 4.99k; Res_ohm: 4990; Value_Code: 4k99; Tolerance_%: 1; Power_W: 0.1; Value2: 0.1W; VDC_V: 75; TempCo: 100 ppm/C; SizeArea_mm2: 1.28; SizeX_mm: 1.6; SizeY_mm: 0.8; EIA_Code: E96; U/M: EA; AEC Category: Q200
R40 = RC0603FR-0724K3L: RES, 24.3 k, 1%, 0.1 W, 0603; Manufacturer: Yageo America; CompType: Resistor; Value: 24.3k; Res_ohm: 24300; Value_Code: 24k3; Tolerance_%: 1; Power_W: 0.1; Value2: 0.1W; VDC_V: 150; TempCo: 200 ppm/C; SizeArea_mm2: 1.28; SizeX_mm: 1.6; SizeY_mm: 0.8; EIA_Code: E96; U/M: EA; AEC Category: Q200
R41 = ERJ-6RQF1R2V: RES, 1.20, 1%, 0.125 W, 0805; Manufacturer: Panasonic; CompType: Resistor; Value: 1.20; Res_ohm: 1.2; Value_Code: 1R20; Tolerance_%: 1; Power_W: 0.125; Value2: 0.125W; TempCo: 200 ppm/C; SizeArea_mm2: 2.5; SizeX_mm: 2; SizeY_mm: 1.25; SizeZ_mm: 1.45; U/M: EA; AEC Category: Q200
R42 = CRCW06033K32FKEA: RES, 3.32 k, 1%, 0.1 W, 0603; Manufacturer: Vishay-Dale; CompType: Resistor; Value: 3.32k; Res_ohm: 3320; Value_Code: 3k32; Tolerance_%: 1; Power_W: 0.1; Value2: 0.1W; VDC_V: 75; TempCo: 100 ppm/C; SizeArea_mm2: 1.28; SizeX_mm: 1.6; SizeY_mm: 0.8; EIA_Code: E96; U/M: EA; AEC Category: Q200
RF1 = PWR4522AS10R0JA: RES, 10, 5%, 32W, Fusible, TH; Manufacturer: Bourns; SymbolCreator: a0412235; CompType: Fusible Resistor; Value: 10; Value_Code: 10R0; Tolerance_%: 5; Power_W: 3; Value2: 3W; TempCo: 90 ppm/C; EIA_Code: E24; U/M: EA
RF2 RF3 = PWR4522AS10R0JA: RES, 10, 5%, 2 W, Fusible, TH; Manufacturer: Bourns; SymbolCreator: a0412235; CompType: Fusible Resistor; Value: 10; Value_Code: 10R0; Tolerance_%: 5; Power_W: 3; Value2: 3W; TempCo: 90 ppm/C; EIA_Code: E24; U/M: EA
RV1-RV3 = S10K275E2: Varistor 275V RMS 10MM Radial, TH; Manufacturer: EPCOS Inc; SymbolCreator: a0412235
T1 = 750316395: Transformer, 1100 uH, TH; Manufacturer: Wurth Elektronik; SymbolCreator: Altium; Value: 1.1mH; Lp: 1100; DCR_ohm: 3.65; Ns1toNp: 0.067; Ns2toNp: 0.089; Rs1: 0.02; Rs2: 0.075; SizeAreaWB_mm2: 653.4; SizeArea_mm2: 555; SizeX_mm: 25; SizeY_mm: 22.2; SizeZ_mm: 16
TP1 TP3 = 1503-2: Terminal, Turret, TH, Double; Manufacturer: Keystone; CompType: Turret Terminal
TP2 TP4 TP6 TP8 = 1503-2: Terminal, Turret, TH, Double; Manufacturer: Keystone; CompType: Turret Terminal; U/M: EA
TP5 TP9 TP10 = 5000: Test Point, Miniature, Red, TH; Manufacturer: Keystone; CompType: Test Point Loop; ContactFinish: Silver
TP7 = 5001: Test Point, Miniature, Black, TH; Manufacturer: Keystone; CompType: Test Point Loop; ContactFinish: Silver
U1 = UCC28600D: Quasi-Resonant Flyback Green-Mode Controller with Current Control, 99 % Duty Cycle, -40 to +105 degC, 8-pin SOIC (D), Green (RoHS & no Sb/Br); Manufacturer: Texas Instruments; Alternate PartNumber: Equivalent; Duty Cycle(Max)(%): 99; Frequency(Max)(kHz): 130; Rating: Catalog; Regulated Outputs(#): 1; SubFamily: PWM Controller; UVLO Thresholds On/Off(V): 10.3/9.3
U2 = FOD817AS: Optocoupler, 5 kV, 80-160% CTR, SMT; Manufacturer: Fairchild Semiconductor; CTR (Min): 80%; CTR (Max): 160%; Voltage_Isolation_Vrms: 5000V
U3 = LMV431AIMF/NOPB: Low-Voltage (1.24V) Adjustable Precision Shunt Regulators, 3-pin SOT-23, Pb-Free; Manufacturer: Texas Instruments; PackageTopMarking: RLA*XTT; PowerWise: N; CompType: MiscPower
